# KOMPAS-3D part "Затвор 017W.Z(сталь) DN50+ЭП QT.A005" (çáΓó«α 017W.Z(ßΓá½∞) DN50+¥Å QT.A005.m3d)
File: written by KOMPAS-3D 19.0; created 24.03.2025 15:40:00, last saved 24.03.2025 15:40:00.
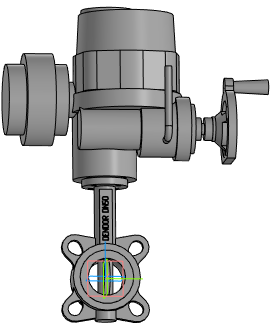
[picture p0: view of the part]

Document properties: Полное имя файла: Затвор 017W.Z(сталь) DN50+ЭП QT.A005.a3d

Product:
- Part/product: Затвор 017W.Z(сталь) DN50+ЭП QT.A005
    Масса: 38.668

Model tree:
1. Операция без истории:1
